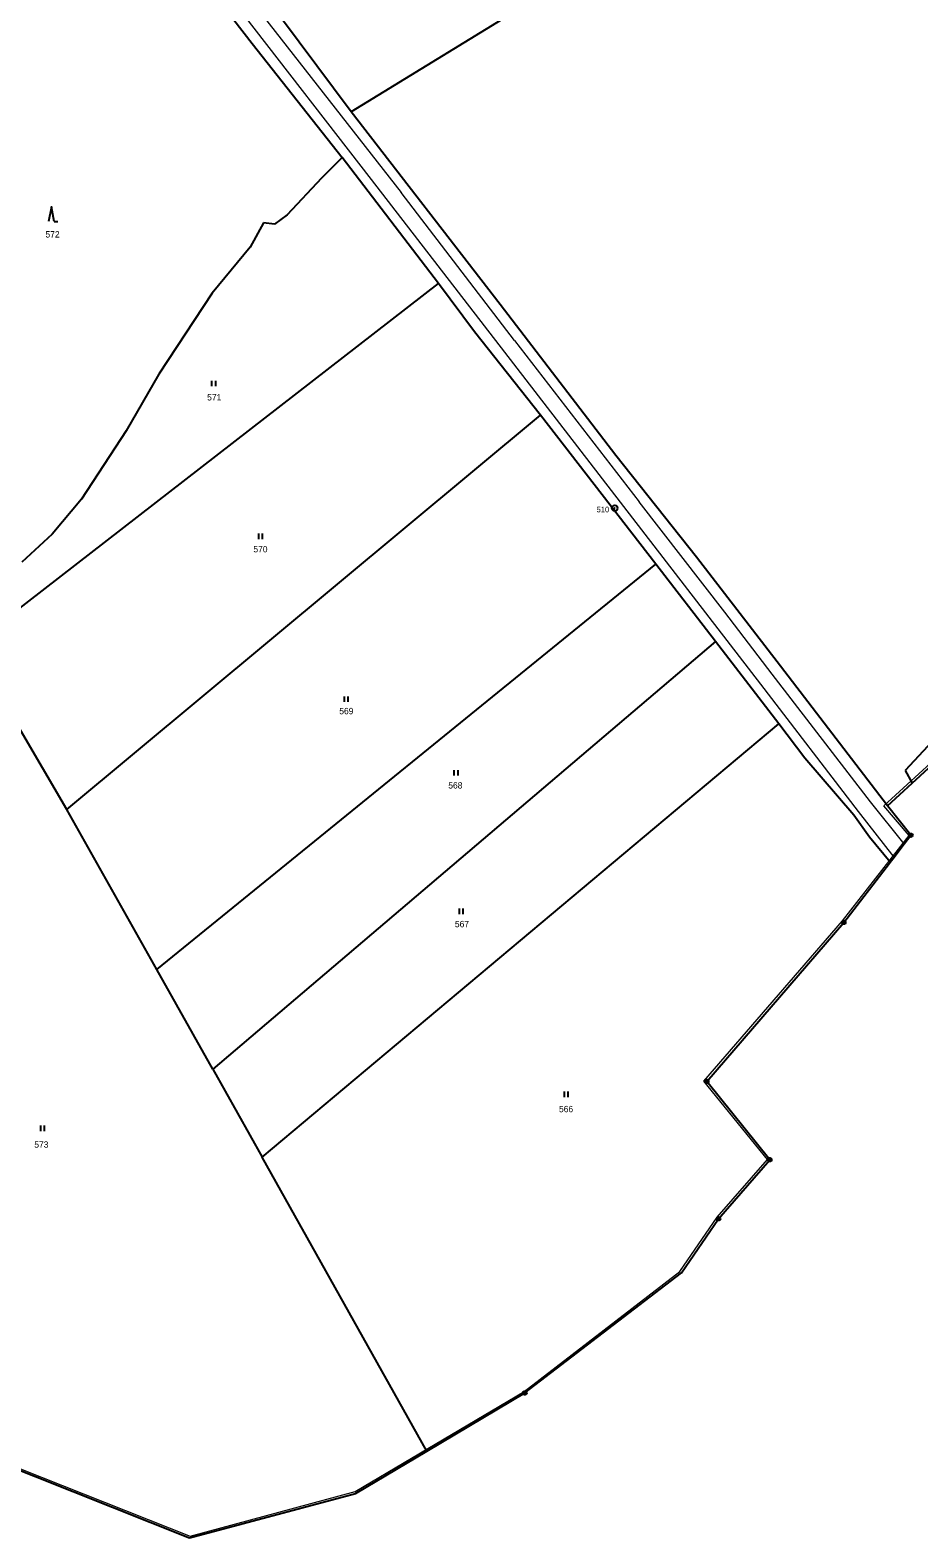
# Model space of a CAD drawing. Extents: x -653193 to -651624, y -1092017 to -1090260.
# Drawn here: x -652647.5 to -652409.3, y -1092002.5 to -1091598.3 of the extents above; entities that cross this region are included whole.
import ezdxf
from ezdxf.enums import TextEntityAlignment as Align

# ---------------------------------------------------------------- set-up
doc = ezdxf.new("R2010")
doc.units = 0
doc.header["$LTSCALE"] = 0.68
for name, color, linetype, lineweight in [('1', 7, 'Continuous', 25), ('3', 7, 'Continuous', 25), ('4', 7, 'Continuous', 13), ('8', 7, 'Continuous', 25)]:
    doc.layers.add(name, color=color, linetype=linetype, lineweight=lineweight)
doc.layers.add('2', color=7, linetype='Continuous')

msp = doc.modelspace()

# ---------------------------------------------------------------- linework, layer by layer
at = {"layer": '1'}
for p, q in [((-652620.84, -1091559.51), (-652587.97, -1091601.84)), ((-652561.46, -1091620.18), (-652586.29, -1091586.79)), ((-652502.91, -1091584.25), (-652561.46, -1091620.18)), ((-652587.97, -1091601.84), (-652563.87, -1091632.43)), ((-652521.47, -1091671.9), (-652561.46, -1091620.18)), ((-652563.87, -1091632.43), (-652569.35, -1091638)), ((-652538.01, -1091666.2), (-652563.87, -1091632.43)), ((-652569.35, -1091638), (-652578.57, -1091647.81)), ((-652578.57, -1091647.81), (-652581.94, -1091650.34)), ((-652584.9, -1091649.92), (-652588.5, -1091656.47)), ((-652581.94, -1091650.34), (-652584.9, -1091649.92)), ((-652588.5, -1091656.47), (-652598.71, -1091668.84)), ((-652663.3, -1091763.35), (-652538.01, -1091666.2)), ((-652528.34, -1091679.15), (-652538.01, -1091666.2)), ((-652598.71, -1091668.84), (-652612.97, -1091690.5)), ((-652490.46, -1091712.38), (-652521.47, -1091671.9)), ((-652510.68, -1091701.55), (-652528.34, -1091679.15)), ((-652612.97, -1091690.5), (-652621.73, -1091705.76)), ((-652637.66, -1091807.25), (-652510.68, -1091701.55)), ((-652479.71, -1091741.43), (-652510.68, -1091701.55)), ((-652621.73, -1091705.76), (-652633.7, -1091724.09)), ((-652468.82, -1091739.62), (-652490.46, -1091712.38)), ((-652633.7, -1091724.09), (-652641.56, -1091733.43)), ((-652641.56, -1091733.43), (-652649.7, -1091740.97)), ((-652446.3, -1091768.82), (-652468.82, -1091739.62)), ((-652613.54, -1091850.11), (-652479.71, -1091741.43)), ((-652463.74, -1091762.18), (-652479.71, -1091741.43)), ((-652411.02, -1091800.15), (-652346.65, -1091741.1)), ((-652637.66, -1091807.25), (-652663.3, -1091763.35)), ((-652463.74, -1091762.18), (-652598.52, -1091876.89)), ((-652446.75, -1091784.28), (-652463.74, -1091762.18)), ((-652417.7, -1091806.27), (-652446.3, -1091768.82)), ((-652585.31, -1091900.42), (-652446.75, -1091784.28)), ((-652439.77, -1091793.46), (-652446.75, -1091784.28)), ((-652403.23, -1091786.47), (-652412.95, -1091796.78)), ((-652426.69, -1091808.78), (-652439.77, -1091793.46)), ((-652412.95, -1091796.78), (-652411.02, -1091800.15)), ((-652417.7, -1091806.27), (-652411.02, -1091800.15)), ((-652613.54, -1091850.11), (-652637.66, -1091807.25)), ((-652422.45, -1091814.64), (-652426.69, -1091808.78)), ((-652411.39, -1091814.15), (-652417.7, -1091806.27)), ((-652416.92, -1091821.36), (-652422.45, -1091814.64)), ((-652415.89, -1091820.02), (-652413.17, -1091816.47)), ((-652413.17, -1091816.47), (-652411.39, -1091814.15)), ((-652429.36, -1091837.53), (-652417.11, -1091821.6)), ((-652417.11, -1091821.6), (-652416.92, -1091821.36)), ((-652416.92, -1091821.36), (-652415.89, -1091820.02)), ((-652466.11, -1091880.18), (-652429.36, -1091837.53)), ((-652598.52, -1091876.89), (-652613.54, -1091850.11)), ((-652598.52, -1091876.89), (-652585.31, -1091900.42)), ((-652449.22, -1091901.14), (-652466.11, -1091880.18)), ((-652541.11, -1091979.24), (-652585.31, -1091900.42)), ((-652462.96, -1091916.98), (-652449.22, -1091901.14)), ((-652472.86, -1091931.49), (-652462.96, -1091916.98)), ((-652514.85, -1091963.68), (-652472.86, -1091931.49)), ((-652541.11, -1091979.24), (-652514.85, -1091963.68)), ((-652684.85, -1091970.65), (-652604.79, -1092002.52)), ((-652560.3, -1091990.6), (-652541.11, -1091979.24)), ((-652604.79, -1092002.52), (-652560.3, -1091990.6))]:
    msp.add_line(p, q, dxfattribs=at)
at = {"layer": '3'}
for p, q in [((-652641.02, -1091649.63), (-652640.024, -1091649.63)), ((-652598.721, -1091693.79), (-652598.721, -1091692.29)), ((-652597.72, -1091693.79), (-652597.72, -1091692.29)), ((-652586.151, -1091734.76), (-652586.151, -1091733.26)), ((-652585.15, -1091734.76), (-652585.15, -1091733.26)), ((-652563.201, -1091778.42), (-652563.201, -1091776.92)), ((-652562.2, -1091778.42), (-652562.2, -1091776.92)), ((-652533.771, -1091798.17), (-652533.771, -1091796.67)), ((-652532.77, -1091798.17), (-652532.77, -1091796.67)), ((-652532.401, -1091835.27), (-652532.401, -1091833.77)), ((-652531.4, -1091835.27), (-652531.4, -1091833.77)), ((-652504.231, -1091884.36), (-652504.231, -1091882.86)), ((-652503.23, -1091884.36), (-652503.23, -1091882.86)), ((-652644.601, -1091893.5), (-652644.601, -1091892)), ((-652643.6, -1091893.5), (-652643.6, -1091892))]:
    msp.add_line(p, q, dxfattribs=at)
msp.add_lwpolyline([(-652641.02, -1091649.63), (-652641.77, -1091645.63), (-652642.52, -1091649.63)], dxfattribs=at)
at = {"layer": '4'}
for p, q in [((-652588.22, -1091590.44), (-652548.06, -1091641.81)), ((-652555.93, -1091638.33), (-652590.18, -1091594.17)), ((-652520.23, -1091684.68), (-652555.93, -1091638.33)), ((-652517.61, -1091681.52), (-652548.06, -1091641.81)), ((-652517.61, -1091681.52), (-652484.18, -1091724.77)), ((-652451.59, -1091773.68), (-652520.23, -1091684.68)), ((-652461.3, -1091754.37), (-652484.18, -1091724.77)), ((-652448.57, -1091770.99), (-652461.3, -1091754.37)), ((-652422.17, -1091805.17), (-652448.57, -1091770.99)), ((-652425.41, -1091807.82), (-652451.59, -1091773.68)), ((-652413.17, -1091816.47), (-652422.17, -1091805.17)), ((-652415.89, -1091820.02), (-652425.41, -1091807.82))]:
    msp.add_line(p, q, dxfattribs=at)
msp.add_lwpolyline([(-652684.79, -1091970.22), (-652604.59, -1092002.09), (-652560.33, -1091990.1), (-652515.03, -1091963.25), (-652473.3, -1091931.15), (-652463.33, -1091916.53), (-652449.81, -1091901.05), (-652466.86, -1091880.08), (-652429.72, -1091837.09), (-652411.86, -1091814.26), (-652418.64, -1091806.23), (-652346.74, -1091740.45)], dxfattribs=at)
at = {"layer": '8'}
for centre, radius in [((-652490.77, -1091726.4498), 0.75), ((-652490.77, -1091726.4498), 0.03), ((-652411.39, -1091814.1499), 0.5), ((-652411.39, -1091814.1499), 0.0303), ((-652429.36, -1091837.5299), 0.5), ((-652429.36, -1091837.5299), 0.0303), ((-652466.11, -1091880.1799), 0.5), ((-652466.11, -1091880.1799), 0.0303), ((-652449.22, -1091901.1399), 0.5), ((-652449.22, -1091901.1399), 0.0303), ((-652462.96, -1091916.9799), 0.5), ((-652462.96, -1091916.9799), 0.0303), ((-652514.85, -1091963.6799), 0.5), ((-652514.85, -1091963.6799), 0.0303)]:
    msp.add_circle(centre, radius, dxfattribs=at)

# ---------------------------------------------------------------- texts
at = {"layer": '2'}
for s, p in [('572', (-652641.459, -1091653.895)), ('571', (-652598.119, -1091697.585)), ('570', (-652585.729, -1091738.315)), ('569', (-652562.709, -1091781.705)), ('568', (-652533.489, -1091801.625)), ('567', (-652531.719, -1091838.815)), ('566', (-652503.819, -1091888.405)), ('573', (-652644.459, -1091897.925))]:
    msp.add_text(s, height=1.7, dxfattribs=at).set_placement(p, align=Align.CENTER)
at = {"layer": '8'}
msp.add_text('510', height=1.5, dxfattribs=at).set_placement((-652492.269, -1091727.567), align=Align.RIGHT)

doc.saveas('drawing.dxf')
